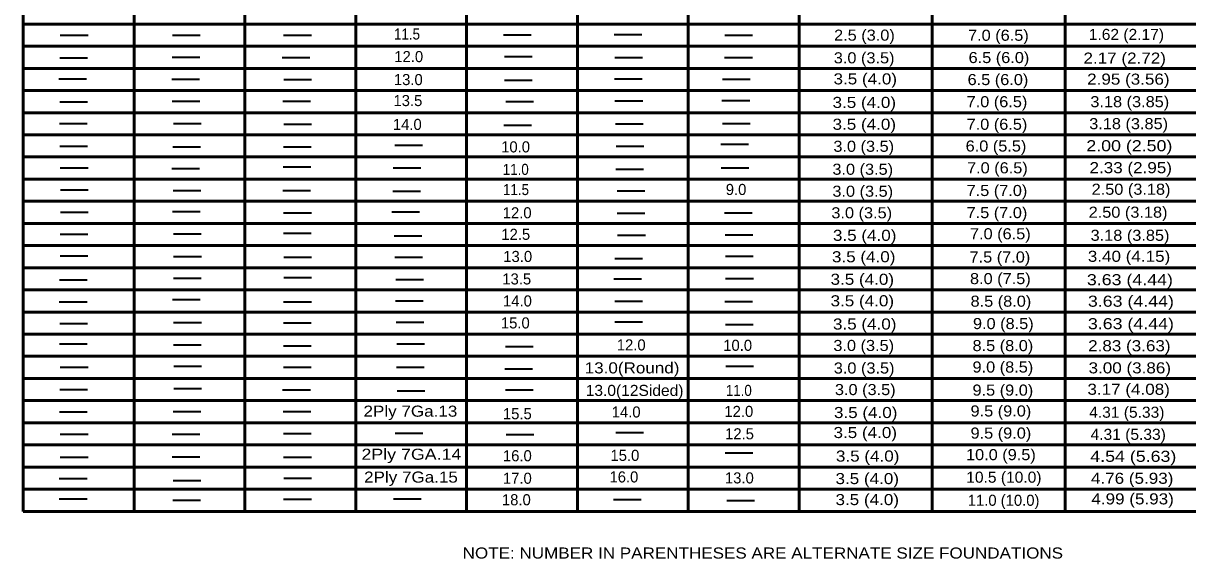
# Model space of a CAD drawing. Extents: x -560 to 120, y 26 to 466.
# Drawn here: x -267.6 to -57.5, y 258.7 to 355.4 of the extents above; entities that cross this region are included whole.
import ezdxf
from ezdxf.enums import TextEntityAlignment as Align

# ---------------------------------------------------------------- set-up
doc = ezdxf.new("R2010")
doc.units = 0
doc.header["$LTSCALE"] = 0.8
doc.layers.add('1', color=7, linetype='Continuous', lineweight=53)

msp = doc.modelspace()

# ---------------------------------------------------------------- linework, layer by layer
at = {"layer": '1'}
for p, q in [((-267.5954, 440.21), (-267.5954, 267.21)), ((-127.5954, 440.21), (-127.5954, 267.21)), ((-247.5954, 434.71), (-247.5954, 267.21)), ((-227.5954, 434.71), (-227.5954, 267.21)), ((-207.5954, 434.71), (-207.5954, 267.21)), ((-187.5954, 434.71), (-187.5954, 267.21)), ((-167.5954, 434.71), (-167.5954, 267.21)), ((-147.5954, 434.71), (-147.5954, 267.21)), ((-103.5954, 431.71), (-103.5954, 267.21)), ((-79.5954, 431.71), (-79.5954, 267.21)), ((-267.5954, 355.21), (-7.6086, 355.21)), ((-267.5954, 351.21), (-7.6086, 351.21)), ((-267.5954, 347.21), (-7.6086, 347.21)), ((-267.5954, 343.21), (-7.6086, 343.21)), ((-267.5954, 339.21), (-7.6086, 339.21)), ((-267.5954, 335.21), (-7.6086, 335.21)), ((-267.5954, 331.21), (-7.6086, 331.21)), ((-267.5954, 327.21), (-7.6086, 327.21)), ((-267.5954, 323.21), (-7.6086, 323.21)), ((-267.5954, 319.21), (-7.6086, 319.21)), ((-267.5954, 315.21), (-7.6086, 315.21)), ((-267.5954, 311.21), (-7.6086, 311.21)), ((-267.5954, 307.21), (-7.6086, 307.21)), ((-267.5954, 303.21), (-7.6086, 303.21)), ((-267.5954, 299.21), (-7.6086, 299.21)), ((-267.5954, 295.21), (-7.6086, 295.21)), ((-267.5954, 291.21), (-7.6086, 291.21)), ((-267.5954, 287.21), (-7.6086, 287.21)), ((-267.5954, 283.21), (-7.6086, 283.21)), ((-267.5954, 279.21), (-7.6086, 279.21)), ((-267.5954, 275.21), (-7.6086, 275.21)), ((-267.5954, 271.21), (-7.6086, 271.21)), ((-267.5954, 267.21), (-7.5954, 267.21))]:
    msp.add_line(p, q, dxfattribs=at)
at = {"layer": '1', "lineweight": 35}
for p, q in [((-260.9156, 353.1963), (-255.9156, 353.1963)), ((-240.6887, 353.1963), (-235.6887, 353.1963)), ((-220.6141, 353.1963), (-215.6141, 353.1963)), ((-180.9503, 353.2722), (-175.9503, 353.2722)), ((-160.9787, 353.3483), (-155.9787, 353.3483)), ((-141.0069, 353.2208), (-136.0069, 353.2208)), ((-261.0187, 349.1255), (-256.0187, 349.1255)), ((-240.7159, 349.2531), (-235.7159, 349.2531)), ((-220.8692, 349.2014), (-215.8692, 349.2014)), ((-180.7712, 349.3562), (-175.7712, 349.3562)), ((-160.8756, 349.15), (-155.8756, 349.15)), ((-141.0342, 349.1744), (-136.0342, 349.1744)), ((-261.1977, 345.3098), (-256.1977, 345.3098)), ((-240.7918, 345.2582), (-235.7918, 345.2582)), ((-220.5624, 345.2337), (-215.5624, 345.2337)), ((-180.7725, 345.0698), (-175.7725, 345.0698)), ((-160.9272, 345.3249), (-155.9272, 345.3249)), ((-141.4387, 345.2721), (-136.4387, 345.2721)), ((-260.9942, 341.1873), (-255.9942, 341.1873)), ((-240.743, 341.3148), (-235.743, 341.3148)), ((-220.7687, 341.3148), (-215.7687, 341.3148)), ((-180.5187, 341.228), (-175.5187, 341.228)), ((-160.8252, 341.33), (-155.8252, 341.33)), ((-141.5146, 341.4319), (-136.5146, 341.4319)), ((-261.0702, 337.2439), (-256.0702, 337.2439)), ((-240.4879, 337.244), (-235.4879, 337.244)), ((-220.5652, 337.1409), (-215.5652, 337.1409)), ((-180.8973, 336.9497), (-175.8973, 336.9497)), ((-160.7477, 337.2022), (-155.7477, 337.2022)), ((-141.4114, 337.2294), (-136.4114, 337.2294)), ((-260.9942, 333.1732), (-255.9942, 333.1732)), ((-240.5911, 333.0456), (-235.5911, 333.0456)), ((-220.6412, 333.0456), (-215.6412, 333.0456)), ((-200.5624, 333.3248), (-195.5624, 333.3248)), ((-160.6204, 333.1777), (-155.6204, 333.1777)), ((-141.7426, 333.5041), (-136.7426, 333.5041)), ((-260.9183, 329.2298), (-255.9183, 329.2298)), ((-240.8191, 329.1538), (-235.8191, 329.1538)), ((-220.6927, 329.4089), (-215.6927, 329.4089)), ((-200.8396, 329.2331), (-195.8396, 329.2331)), ((-160.6745, 329.0309), (-155.6745, 329.0309)), ((-141.6924, 329.2319), (-136.6924, 329.2319)), ((-260.8911, 325.2594), (-255.8911, 325.2594)), ((-240.5639, 325.1562), (-235.5639, 325.1562)), ((-220.7442, 325.159), (-215.7442, 325.159)), ((-200.9155, 325.0577), (-195.9155, 325.0577)), ((-160.4168, 325.1054), (-155.4168, 325.1054)), ((-260.891, 321.2402), (-255.891, 321.2402)), ((-240.6914, 321.3677), (-235.6914, 321.3677)), ((-220.6167, 321.137), (-215.6167, 321.137)), ((-201.096, 321.29), (-196.096, 321.29)), ((-160.4438, 321.0347), (-155.4438, 321.0347)), ((-141.0893, 321.1393), (-136.0893, 321.1393)), ((-240.4879, 317.3212), (-235.4879, 317.3212)), ((-220.6412, 317.4488), (-215.6412, 317.4488)), ((-260.9671, 317.2452), (-255.9671, 317.2452)), ((-200.6874, 316.9677), (-195.6874, 316.9677)), ((-160.3447, 317.0887), (-155.3447, 317.0887)), ((-140.9399, 317.1471), (-135.9399, 317.1471)), ((-260.9671, 313.3779), (-255.9671, 313.3779)), ((-240.4635, 313.226), (-235.4635, 313.226)), ((-220.5652, 313.0984), (-215.5652, 313.0984)), ((-200.5597, 313.1249), (-195.5597, 313.1249)), ((-140.8626, 313.3262), (-135.8626, 313.3262)), ((-160.8756, 312.8503), (-155.8756, 312.8503)), ((-261.0431, 309.0276), (-256.0431, 309.0276)), ((-240.488, 309.307), (-235.488, 309.307)), ((-220.5651, 309.4346), (-215.5651, 309.4346)), ((-200.3833, 309.0632), (-195.3833, 309.0632)), ((-161.056, 309.1842), (-156.056, 309.1842)), ((-140.8587, 309.2643), (-135.8587, 309.2643)), ((-261.0946, 305.0572), (-256.0946, 305.0572)), ((-240.6941, 305.4913), (-235.6941, 305.4913)), ((-220.6167, 305.0327), (-215.6167, 305.0327)), ((-200.436, 305.2229), (-195.436, 305.2229)), ((-160.8754, 305.1674), (-155.8754, 305.1674)), ((-141.0314, 305.0953), (-136.0314, 305.0953)), ((-260.9915, 301.1653), (-255.9915, 301.1653)), ((-240.4635, 301.2929), (-235.4635, 301.2929)), ((-220.6656, 301.2413), (-215.6656, 301.2413)), ((-200.3097, 301.3803), (-195.3097, 301.3803)), ((-160.8754, 301.4318), (-155.8754, 301.4318)), ((-140.9052, 300.9729), (-135.9052, 300.9729)), ((-261.043, 297.4527), (-256.043, 297.4527)), ((-240.4852, 297.298), (-235.4852, 297.298)), ((-220.6656, 297.119), (-215.6656, 297.119)), ((-200.1836, 297.4807), (-195.1836, 297.4807)), ((-180.5675, 296.9998), (-175.5675, 296.9998)), ((-260.9155, 293.2788), (-255.9155, 293.2788)), ((-240.4582, 293.4063), (-235.4582, 293.4063)), ((-220.6657, 293.2788), (-215.6657, 293.2788)), ((-200.2596, 293.2319), (-195.2596, 293.2319)), ((-180.6964, 292.9289), (-175.6964, 292.9289)), ((-140.8509, 293.4368), (-135.8509, 293.4368)), ((-260.9916, 289.2078), (-255.9916, 289.2078)), ((-240.4582, 289.4115), (-235.4582, 289.4115)), ((-220.7932, 289.1563), (-215.7932, 289.1563)), ((-200.1578, 288.9845), (-195.1578, 288.9845)), ((-180.5946, 289.1624), (-175.5946, 289.1624)), ((-261.0675, 285.213), (-256.0675, 285.213)), ((-240.5586, 285.2646), (-235.5586, 285.2646)), ((-220.6901, 285.2646), (-215.6901, 285.2646)), ((-260.9154, 281.1422), (-255.9154, 281.1422)), ((-240.7377, 281.1422), (-235.7377, 281.1422)), ((-220.6656, 281.2697), (-215.6656, 281.2697)), ((-200.5157, 281.3248), (-195.5157, 281.3248)), ((-180.4849, 281.0887), (-175.4849, 281.0887)), ((-160.6977, 281.478), (-155.6977, 281.478)), ((-140.9268, 277.7629), (-135.9268, 277.7629)), ((-260.9155, 276.9683), (-255.9155, 276.9683)), ((-240.7377, 277.0713), (-235.7377, 277.0713)), ((-220.614, 277.0197), (-215.614, 277.0197)), ((-220.5896, 273.204), (-215.5896, 273.204)), ((-261.0947, 273.1281), (-256.0947, 273.1281)), ((-240.5341, 272.7969), (-235.5341, 272.7969)), ((-261.0947, 269.4642), (-256.0947, 269.4642)), ((-240.6372, 269.2091), (-235.6372, 269.2091)), ((-220.614, 269.3882), (-215.614, 269.3882)), ((-200.8141, 269.4472), (-195.8141, 269.4472)), ((-161.0778, 269.3671), (-156.0778, 269.3671)), ((-140.6459, 269.1892), (-135.6459, 269.1892))]:
    msp.add_line(p, q, dxfattribs=at)

# ---------------------------------------------------------------- texts
at = {"layer": '1'}
for s, width, p in [('11.5', 0.9, (-198.3494, 352.4165)), ('2.5 (3.0)', 1.1, (-115.8132, 352.2152)), ('7.0 (6.5)', 1.1, (-91.6424, 352.192)), ('1.62 (2.17)', 1.05, (-68.5401, 352.3458)), ('3.0 (3.5)', 1.1, (-115.8639, 348.1194)), ('6.5 (6.0)', 1.1, (-91.5405, 348.1717)), ('2.17 (2.72)', 1.15, (-68.8455, 348.0713)), ('3.5 (4.0)', 1.15, (-115.6603, 344.3194)), ('6.5 (6.0)', 1.1, (-91.7184, 344.1932)), ('2.95 (3.56)', 1.15, (-68.1845, 344.2707)), ('3.5 (4.0)', 1.15, (-115.8382, 340.0707)), ('7.0 (6.5)', 1.1, (-91.8963, 340.199)), ('3.18 (3.85)', 1.1, (-67.9306, 340.1999)), ('3.18 (3.85)', 1.1, (-68.1342, 336.2262)), ('3.5 (4.0)', 1.15, (-115.8381, 336.1223)), ('7.0 (6.5)', 1.1, (-91.8963, 336.1233)), ('3.0 (3.5)', 1.1, (-115.94, 332.1435)), ('6.0 (5.5)', 1.1, (-92.0729, 332.1963)), ('2.00 (2.50)', 1.2, (-68.0068, 332.2483)), ('11.0', 0.9, (-178.7282, 327.9701)), ('3.0 (3.5)', 1.1, (-116.1191, 327.9966)), ('7.0 (6.5)', 1.1, (-91.8214, 328.2535)), ('2.33 (2.95)', 1.15, (-67.7554, 328.2804)), ('11.5', 0.9, (-178.6805, 324.3311)), ('3.0 (3.5)', 1.1, (-116.1192, 324.0287)), ('7.5 (7.0)', 1.1, (-91.8978, 324.1575)), ('2.50 (3.18)', 1.1, (-67.7037, 324.3874)), ('3.0 (3.5)', 1.1, (-116.2982, 320.1332)), ('7.5 (7.0)', 1.1, (-91.8978, 320.1615)), ('2.50 (3.18)', 1.1, (-68.2398, 320.2392)), ('3.5 (4.0)', 1.15, (-115.7672, 316.0641)), ('7.0 (6.5)', 1.1, (-91.288, 316.345)), ('3.18 (3.85)', 1.1, (-67.8868, 316.0679)), ('3.5 (4.0)', 1.15, (-115.9437, 312.1968)), ('7.5 (7.0)', 1.1, (-91.3642, 312.1485)), ('3.40 (4.15)', 1.15, (-68.0659, 312.2753)), ('3.5 (4.0)', 1.15, (-116.1977, 308.126)), ('8.0 (7.5)', 1.1, (-91.2868, 308.2457)), ('3.63 (4.44)', 1.2, (-67.9087, 308.0536)), ('3.5 (4.0)', 1.15, (-116.1938, 304.2421)), ('8.5 (8.0)', 1.1, (-91.185, 304.1674)), ('3.63 (4.44)', 1.2, (-67.7272, 304.1683)), ('3.5 (4.0)', 1.15, (-115.762, 300.0447)), ('9.0 (8.5)', 1.1, (-90.7533, 300.1222)), ('3.63 (4.44)', 1.2, (-67.7284, 300.1053)), ('3.0 (3.5)', 1.1, (-115.94, 296.1717)), ('8.5 (8.0)', 1.1, (-90.8293, 296.1481)), ('2.83 (3.63)', 1.15, (-68.0068, 296.1238)), ('13.0(Round)', 1.15, (-157.7427, 292.1257)), ('3.0 (3.5)', 1.1, (-115.8639, 292.1011)), ('9.0 (8.5)', 1.1, (-90.8293, 292.2808)), ('3.00 (3.86)', 1.15, (-67.9306, 292.1292)), ('13.0(12Sided)', 1.05, (-157.2864, 288.0548)), ('11.0', 0.9, (-138.4822, 288.0548)), ('3.0 (3.5)', 1.1, (-115.6604, 288.208)), ('9.5 (9.0)', 1.1, (-90.8293, 288.108)), ('3.17 (4.08)', 1.15, (-68.1342, 288.2618)), ('2Ply 7Ga.13', 1.15, (-197.7399, 284.3059)), ('3.5 (4.0)', 1.15, (-115.5842, 284.0616)), ('9.5 (9.0)', 1.1, (-91.185, 284.3426)), ('4.31 (5.33)', 1.05, (-68.4653, 284.1148)), ('3.5 (4.0)', 1.15, (-115.6603, 280.4482)), ('9.5 (9.0)', 1.1, (-91.185, 280.3478)), ('4.31 (5.33)', 1.05, (-68.2114, 280.1201)), ('2Ply 7GA.14', 1.2, (-197.5609, 276.5277)), ('3.5 (4.0)', 1.15, (-115.2286, 276.1995)), ('10.0 (9.5)', 1.1, (-91.186, 276.4548)), ('4.54 (5.63)', 1.2, (-67.2954, 276.1511)), ('2Ply 7Ga.15', 1.15, (-197.6382, 272.3986)), ('3.5 (4.0)', 1.15, (-115.3047, 272.1286)), ('10.5 (10.0)', 1.05, (-90.6515, 272.3845)), ('4.76 (5.93)', 1.15, (-67.499, 272.1819)), ('3.5 (4.0)', 1.15, (-115.3047, 268.3374)), ('4.99 (5.93)', 1.15, (-67.4229, 268.4669)), ('NOTE: NUMBER IN PARENTHESES ARE ALTERNATE SIZE FOUNDATIONS', 1.15, (-134.1443, 258.6835))]:
    msp.add_text(s, height=2, dxfattribs=dict(at, width=width)).set_placement(p, align=Align.CENTER)
for s, p in [('12.0', (-198.0441, 348.3457)), ('13.0', (-198.1202, 344.1892)), ('13.5', (-198.1962, 340.398)), ('14.0', (-198.298, 336.0938)), ('10.0', (-178.7578, 332.0409)), ('9.0', (-138.9743, 324.3447)), ('12.0', (-178.477, 320.1351)), ('12.5', (-178.7308, 316.2421)), ('13.0', (-178.3752, 312.2459)), ('13.5', (-178.5504, 308.1841)), ('14.0', (-178.4268, 304.2152)), ('15.0', (-178.8082, 300.2461)), ('12.0', (-157.8959, 296.2727)), ('10.0', (-138.6858, 296.1965)), ('15.5', (-178.4423, 283.848)), ('14.0', (-158.8107, 284.1618)), ('12.0', (-138.4822, 284.2636)), ('12.5', (-138.3547, 280.2183)), ('16.0', (-178.4435, 276.2568)), ('15.0', (-159.0388, 276.3254)), ('17.0', (-178.4423, 272.1949)), ('16.0', (-159.2167, 272.4325)), ('13.0', (-138.3805, 272.2546)), ('18.0', (-178.6201, 268.3097)), ('11.0 (10.0)', (-90.7019, 268.212))]:
    msp.add_text(s, height=2, dxfattribs=at).set_placement(p, align=Align.CENTER)

doc.saveas('drawing.dxf')
